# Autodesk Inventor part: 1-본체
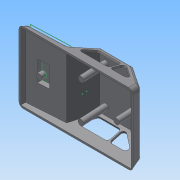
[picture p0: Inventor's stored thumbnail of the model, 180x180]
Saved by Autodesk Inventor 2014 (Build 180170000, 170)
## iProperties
Created: 2015-05
Part Number: 1-본체
Material: Generic
Document SubType Name: Modeling
Designer: Administrator
Density: 1 g/cm^3
Appearance: Default
Author: Administrator
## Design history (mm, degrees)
sketch "스케치1"
  geometry: L1 (-61, 0)-(61, 0); L2 (-61, 0)-(-59.392, 6); L3 (-59.392, 6)-(-17.392, 8.201); L4 (-17.392, 8.201)-(-3.771, 30); L5 (-3.771, 30)-(31, 30); L6 (31, 30)-(58.321, 10); L7 (58.321, 10)-(61, 0); 3 further points
  constraints: 14 end point, 1 coincident, 1 horizontal, 1 midpoint, 1 parallel
  dimensions: "d0" = 122 distance of L1.start L1.end; "d1" = 6 vertical distance of L1.start L2.end; "d2" = 105 deg angle of L1 L2; "d3" = 42 horizontal distance of L2.end L3.end; "d4" = 3 deg angle of L1 L3; "d5" = 30 horizontal distance of L1.end L5.end; "d6" = 125 deg angle of L4 L3; "d7" = 20 vertical distance of L6.end L5.end; "d8" = 105 deg angle of L1 L7; "d9" = 30 distance between parallel lines of L1 L5; "d10" = 58.92148 distance from line of point (0, 0) L7; "d11" = 42.51835 distance from line of point (0, 0) L6
extrude "돌출1" new body sketch "스케치1" stored distance "d12" = 76; taper "d13" = 0 deg
node "작업 평면1"
sketch "스케치2"
  geometry: L1 (0, 38)-(0, -38) reference; L2 (8.201, -38)-(30, -38) reference; L3 (6, -38)-(8.201, -38) reference; L4 (0, -38)-(6, -38) reference; L5 (30, 38)-(8.201, 38) reference; L6 (8.201, 38)-(6, 38) reference; L7 (6, 38)-(0, 38) reference; L8 (30, -38)-(30, 38) reference; L9 (0, -38)-(30, -29.962); L10 (0, 38)-(30, 29.962); L11 (30, 29.962)-(30, 38); L12 (30, -29.962)-(30, -38); 1 further point
  constraints: 8 end point, 2 collinear, 2 point on line
  dimensions: "d15" = 105 deg angle of L1 L9; "d16" = 105 deg angle of L1 L10
extrude "돌출2" cut sketch "스케치2" stored distance "d17" = 76; taper "d18" = 0 deg
feature "쉘1" dims "d19" = 2
node "작업 평면2"
sketch "스케치4"
  geometry: L1 (59.392, 6)-(17.392, 8.201) reference; L2 (50, 6.492)-(48.142, 11.596); L3 (48.142, 11.596)-(32.079, 12.438); L4 (32.079, 12.438)-(30, 7.54); L5 (50, 6.492)-(52.432, -0.19); L6 (30, 7.54)-(27.536, 1.735); L7 (61, 0)-(59.392, 6) reference; L8 (61, 0)-(61, 15.359); L9 (61, 15.359)-(52.326, 15.359); 1 further point
  constraints: 14 end point, 2 collinear, 2 point on line, 1 parallel, 1 perpendicular, 1 vertical
  dimensions: "d22" = 11 distance from line of L8 L2.start; "d23" = 70 deg angle of L2 L9; "d24" = 70 deg angle of L4 L1; "d25" = 20 horizontal distance of L4.end L2.start; "d27" = 5 distance between parallel lines of L1 L3
extrude "돌출3" join sketch "스케치4" stored distance "d28" = 26; taper "d29" = 0 deg
sketch "스케치5"
  geometry: L1 (43.608, 8.49)-(57.229, 31.058) reference; L2 (92, 31.058)-(119.321, 10.353) reference; L3 (57.229, 31.058)-(92, 31.058) reference; L4 (43.608, 8.49)-(51.325, 8.49); L5 (59.176, 24.609)-(53.744, 15.609); L6 (56.313, 11.058)-(81.998, 11.058); L7 (84.998, 14.058)-(84.998, 23.058); L8 (81.998, 26.058)-(61.745, 26.058); L9 (86.311, 23.058)-(86.311, 14.058); L10 (89.311, 11.058)-(101.186, 11.058); L11 (102.998, 16.449)-(91.123, 25.449); L12 (0, 0)-(122, 0) reference; L13 (89.311, 26.058)-(97.253, 26.058); A1 r 3 centre (61.745, 23.058) between (61.745, 26.058) and (59.176, 24.609); A2 r 3 centre (56.313, 14.058) between (53.744, 15.609) and (56.313, 11.058); A3 r 3 centre (81.998, 14.058) between (81.998, 11.058) and (84.998, 14.058); A4 r 3 centre (81.998, 23.058) between (84.998, 23.058) and (81.998, 26.058); A5 r 3 centre (89.311, 23.058) between (91.123, 25.449) and (86.311, 23.058); A6 r 3 centre (89.311, 14.058) between (86.311, 14.058) and (89.311, 11.058); A7 r 3 centre (101.186, 14.058) between (101.186, 11.058) and (102.998, 16.449); 6 further points
  constraints: 18 end point, 15 point on circle, 15 tangent, 10 point on line, 7 centre point, 5 equal radius, 5 parallel, 4 perpendicular, 1 collinear
  dimensions: "d30" = 5 distance between parallel lines of L1 L5; "d31" = 5 distance between parallel lines of L8 L3; "d32" = 34 distance of point (50.998, 11.058) point (84.998, 11.058); "d33" = 5 distance between parallel lines of L11 L2; "d34" = 15 vertical distance of point (60.051, 26.058) point (50.998, 11.058); "d36" = 3 radius of A1; "d50" = 3 radius of A5; "d51" = 15 distance between parallel lines of L10 L13
extrude "돌출4" cut sketch "스케치5" distance "d37" = 2; taper "d38" = 0 deg
node "작업 평면3"
node "작업 평면5"
sketch "스케치8"
  geometry: L1 (-16.085, 26)-(0, 26) reference; L2 (-16.085, 26)-(-16.085, 0) reference; L3 (0, 26)-(0, 0) reference; L4 (0, 0)-(-16.085, 0) reference; L5 (-2, 24)-(-14.085, 24); L6 (-14.085, 24)-(-14.085, 2); L7 (-14.085, 2)-(-2, 2); L8 (-2, 2)-(-2, 24); 1 further point
  constraints: 8 end point, 3 other
  dimensions: "d44" = 2 distance between parallel lines of L5 L1
extrude "돌출5" cut sketch "스케치8" stored distance "d45" = 2; taper "d46" = 0 deg
fillet "모깎기3" dims "d47" = 3
fillet "모깎기4" dims "d48" = 3
fillet "모깎기5" dims "d49" = 3
fillet "모깎기6" dims "d52" = 3
fillet "모깎기7" dims "d53" = 5
sketch "스케치10"
  geometry: L1 (-2, -24)-(-14.085, -24) reference; L2 (-2, -2)-(-2, -24) reference; L3 (-14.085, -2)-(-2, -2) reference; L4 (-14.085, -24)-(-14.085, -2) reference; L5 (-14.085, -24)-(-14.085, -2) reference; L6 (-14.085, -2)-(-2, -2) reference; L7 (-2, -2)-(-2, -24) reference; L8 (-2, -24)-(-14.085, -24) reference; L9 (-26.16, 21.837)-(15.486, 21.253) reference; L10 (-26.16, -47.837)-(-26.16, 21.837) reference; L11 (15.486, -47.253)-(-26.16, -47.837) reference; L12 (15.486, -47.253)-(15.486, 21.253) reference; L13 (-2, -2)-(-2, -24) reference; L14 (-14.085, -2)-(-2, -2) reference; 3 further points
  constraints: 2 midpoint
  node "투영된 루프2"
sketch "스케치11"
  geometry: L1 (41.646, 0.584)-(0, 0) reference; L2 (41.646, 0.584)-(41.646, 69.089) reference; C1 r 3 at (18.117, 34.837); C2 r 3 at (62.848, 14.837); C3 r 3 at (62.848, 54.837); C4 r 3 at (100.88, 34.837); 1 further point
  constraints: 4 centre point, 1 horizontal alignment, 1 vertical alignment
  dimensions: "d56" = 6 diameter of C1; "d57" = 6 diameter of C2; "d58" = 6 diameter of C3; "d59" = 20 vertical distance of C2.centre point (57.544, 34.837); "d60" = 20 vertical distance of C3.centre point (57.544, 34.837); "d61" = 6 diameter of C4; "d62" = 33.41858 distance from line of C4.centre L1; "d63" = 53.9499 distance from line of C3.centre L1; "d64" = 34.57908 distance from line of C1.centre L1; "d65" = 23.52859 distance from line of C1.centre L2
extrude "돌출6" join sketch "스케치11" stored distance "d66" = 1; taper "d67" = 0 deg
sketch "스케치12"
  geometry: C1 r 3 at (0, 0) reference; C2 r 3 at (-38.032, -20) reference; C3 r 3 at (-38.032, 20) reference; 1 further point
extrude "돌출7" join sketch "스케치12" stored distance "d68" = 1; taper "d69" = 0 deg
sketch "스케치13"
  geometry: C1 r 3 at (0, 0) reference; 1 further point
node "솔리드1"
mirror "대칭1"
other parameters: "d21" = 0, "d39" = 0, "d43" = -2
